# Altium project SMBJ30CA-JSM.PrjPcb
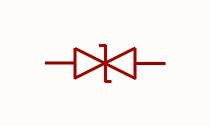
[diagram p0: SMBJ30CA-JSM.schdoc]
1 sheet, 1 parts. Net scope: global (net labels, ports and power ports of the same name join across sheets).

## Sheet SMBJ30CA-JSM.schdoc
size 127 x 101 mm

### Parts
D?  smbj30ca-jsm  [SMB_L4.4-W3.6-LS5.3-BI]  (value not drawn)

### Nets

Not connected (* = marked no-connect by the designer): D? 1 2

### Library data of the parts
D? = smbj30ca-jsm: 极性:双向;反向截止电压(Vrwm):30V;钳位电压:48.4V;峰值脉冲电流(Ipp):12.4A;峰值脉冲功率(Ppp):600W;击穿电压(VBR):36.8V;; Manufacturer: JSMSEMI(杰盛微); AddInBom: yes; ModelId: 0b05f1e84232498d868b1eafe1bb2917; ModelTransform: 210.2358,142.3979,0,0,0,0,0,0,0; Polarity: 双向; Reverse Stand-Off Voltage (Vrwm): 30V; Clamping Voltage: 48.4V; Peak Pulse Current (Ipp): 12.4A; Peak Pulse Power Dissipation (Ppp): 600W; Voltage - Breakdown: 36.8V; Reverse Leakage Current (Ir): 1uA; Number of Channels: 单路; Type: TVS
